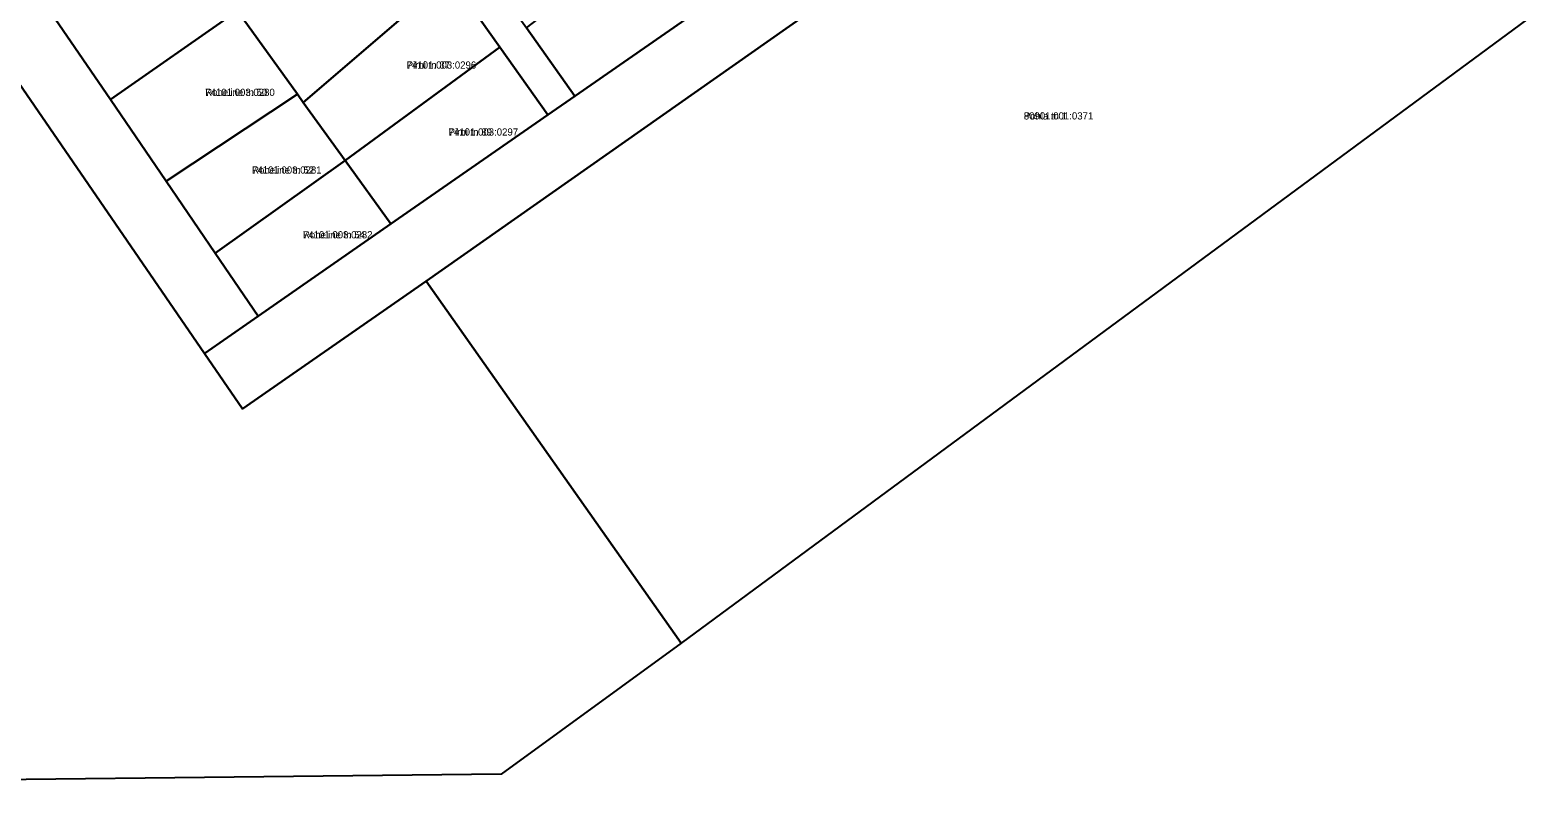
# Model space of a CAD drawing. Extents: x 524000 to 564260, y 6469338 to 6496391.
# Drawn here: x 538860.7 to 539175.1, y 6472786.6 to 6472943.6 of the extents above; entities that cross this region are included whole.
import ezdxf

# ---------------------------------------------------------------- set-up
doc = ezdxf.new("R2010")
doc.units = 0
for name, color, linetype in [('L_AADRESS', 7, 'Continuous'), ('PIIR', 7, 'Continuous'), ('TUNNUS', 7, 'Continuous')]:
    doc.layers.add(name, color=color, linetype=linetype)

msp = doc.modelspace()

# ---------------------------------------------------------------- linework, layer by layer
at = {"layer": 'PIIR'}
for points in [[(539192.75, 6473064.71), (539146.78, 6473034.18), (538943.24, 6472891.21), (538904.95, 6472864.61), (538897.02, 6472876.14), (538908.25, 6472883.95), (538935.88, 6472903.16), (538968.64, 6472925.93), (538974.26, 6472929.84), (539004.27, 6472950.7), (539029.6, 6472968.3), (539035.14, 6472972.15), (539057.88, 6472987.95), (539080.81, 6473003.9), (539086.37, 6473007.8), (539107.07, 6473022.19), (539136.04, 6473042.29), (539141.67, 6473046.21), (539172.02, 6473067.3), (539159.88, 6473083.49), (539148.9, 6473098.13), (539136.07, 6473115.23), (539185.12, 6473155.08)], [(538858.93, 6473092.75), (538871.19, 6473075.42), (538887.92, 6473051.8), (538901.06, 6473033.25), (538913.15, 6473016.17), (538923.28, 6473001.86), (538934.1, 6472986.57), (538943.59, 6472973.16), (538953.55, 6472959.1), (538964.17, 6472944.1), (538974.26, 6472929.84), (538968.64, 6472925.93), (538958.65, 6472940.04), (538948.22, 6472954.77), (538936.1, 6472971.89), (538925.83, 6472986.41), (538915.85, 6473000.49), (538904.99, 6473015.84), (538895.1, 6473029.81), (538882.61, 6473047.46), (538871.15, 6473063.65), (538860.37, 6473078.87)], [(538854.51, 6472962.63), (538865.93, 6472945.92), (538877.41, 6472929.1), (538889.02, 6472912.12), (538899.27, 6472897.1), (538908.25, 6472883.95), (538897.02, 6472876.14), (538851.02, 6472943.09)]]:
    msp.add_lwpolyline(points, dxfattribs=at)
for points in [[(538943.24, 6472891.21), (539146.78, 6473034.18), (539197.65, 6472964.18), (538996.48, 6472815.75)], [(538948.22, 6472954.77), (538917.65, 6472928.53), (538916.43, 6472930.23), (538905.14, 6472945.94), (538936.1, 6472971.89)], [(538964.17, 6472944.1), (538993.1, 6472966.26), (538993.69, 6472965.42), (539004.27, 6472950.7), (538974.26, 6472929.84)], [(538865.93, 6472945.92), (538891.95, 6472964.29), (538894.21, 6472961.15), (538903.93, 6472947.62), (538877.41, 6472929.1)], [(538958.65, 6472940.04), (538926.38, 6472916.38), (538917.65, 6472928.53), (538948.22, 6472954.77)], [(538877.41, 6472929.1), (538903.93, 6472947.62), (538905.14, 6472945.94), (538916.43, 6472930.23), (538889.02, 6472912.12)], [(538851.02, 6472943.09), (538897.02, 6472876.14), (538904.95, 6472864.61), (538943.24, 6472891.21), (538996.48, 6472815.75), (538958.89, 6472788.39), (538797.92, 6472786.58), (538755.72, 6472849.36), (538791.68, 6472884.74), (538822.46, 6472914.98)], [(538968.64, 6472925.93), (538935.88, 6472903.16), (538926.38, 6472916.38), (538958.65, 6472940.04)], [(538889.02, 6472912.12), (538916.43, 6472930.23), (538917.65, 6472928.53), (538926.38, 6472916.38), (538899.27, 6472897.1)], [(538935.88, 6472903.16), (538908.25, 6472883.95), (538899.27, 6472897.1), (538926.38, 6472916.38)]]:
    msp.add_lwpolyline(points, close=True, dxfattribs=at)

# ---------------------------------------------------------------- texts
at = {"layer": 'L_AADRESS'}
for s, p in [('Pirni tn 37', (538939.21, 6472935.57)), ('Roheline tn 50', (538897.2, 6472929.87)), ('Pohla tn 1', (539067.9, 6472924.96)), ('Pirni tn 39', (538947.95, 6472921.6)), ('Roheline tn 52', (538906.96, 6472913.67)), ('Roheline tn 54', (538917.58, 6472900.16))]:
    msp.add_text(s, height=1.5, dxfattribs=at).set_placement(p)
at = {"layer": 'TUNNUS'}
for s, p in [('74101:003:0296', (538939.21, 6472935.57)), ('74101:003:0280', (538897.2, 6472929.87)), ('80901:001:0371', (539067.9, 6472924.96)), ('74101:003:0297', (538947.95, 6472921.6)), ('74101:003:0281', (538906.96, 6472913.67)), ('74101:003:0282', (538917.58, 6472900.16))]:
    msp.add_text(s, height=1.5, dxfattribs=at).set_placement(p)

doc.saveas('drawing.dxf')
